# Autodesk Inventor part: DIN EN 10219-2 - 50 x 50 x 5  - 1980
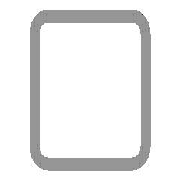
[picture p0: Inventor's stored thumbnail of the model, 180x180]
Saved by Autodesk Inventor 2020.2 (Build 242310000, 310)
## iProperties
IsCustomPart: 1
_CCFamilyMember: 16
_CCFamilyDisplayName: DIN EN 10219-2 (Quadratisches Hohlprofil - Kaltgeformt) - Kaltgeformte, geschweißte Baustahl-Hohlprofile aus unlegiertem Feinkorn-Baustahl
_FrameMemberDoc: Frame Member File
_Version: 15.0.0
_GetPNFromCC: 1
Created: 2019-01
Part Number: DIN EN 10219-2 - 50 x 50 x 5  - 1980
Material: Stahl, weich
Description: Kaltgeformte, geschweißte Baustahl-Hohlprofile aus unlegiertem Feinkorn-Baustahl
Document SubType Name: Modeling
Standard: DIN
Designer: lutzd
Standard Revision: 2006-07
Standards Organization: DIN
Language: de-DE
Size Designation: 50 x 50 x 5
Categories: <MemberInstance><Categories><Category DisplayName="Profile" InternalName="089c4875-fa83-4c05-b084-43b9cc11f5ed" Mnemonic="GRDR"><CategoryParameter DisplayName="
Stock Number: 50 x 50 x 5
Mass: 12983.3 g
Surface Area: 6638.25 cm^2
Volume: 1653.92 cm^3
Density: 7.85 g/cm^3
Appearance: Semi-Polished(8)
G_W: 50,000 mm
G_H: 50,000 mm
DocNumber: ADSK-014372
Folder: .
Mass: 12,983 kg
VLT_Material: Stahl, weich
+D1DB0533-E9D4-4803-9B6B-234758CD5357+SCHNITTDETAIL1: Schnittwinkel 90,00 grd
Dimensions: 50x50x1980 mm
G_L: 1980,000 mm
+D0B73FBA-8EAB-436B-AC1B-9B953FEEEDB6+SCHNITTDETAIL3: Schnittwinkel 90,00 grd
Title: Profil-Bauteil
Author: lutzd
Revision Number: -
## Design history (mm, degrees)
node "Startebene"
node "Endebene"
sketch "Skizze"
  geometry: L1 (-25, -15)-(-25, 15); L2 (-15, 25)-(15, 25); L3 (25, 15)-(25, -15); L4 (15, -25)-(-15, -25); L5 (-15, 20)-(15, 20); L6 (20, 15)-(20, -15); L7 (15, -20)-(-15, -20); L8 (-20, -15)-(-20, 15); L9 (0, 37.899)-(0, -37.899) reference; L10 (-37.899, 0)-(37.899, 0) reference; A1 r 10 centre (-15, -15) between (-25, -15) and (-15, -25); A2 r 10 centre (-15, 15) between (-15, 25) and (-25, 15); A3 r 10 centre (15, 15) between (25, 15) and (15, 25); A4 r 10 centre (15, -15) between (15, -25) and (25, -15); A5 r 5 centre (-15, 15) between (-15, 20) and (-20, 15); A6 r 5 centre (15, 15) between (20, 15) and (15, 20); A7 r 5 centre (15, -15) between (15, -20) and (20, -15); A8 r 5 centre (-15, -15) between (-20, -15) and (-15, -20)
  constraints: 16 end point, 16 point on circle, 8 centre point, 8 tangent, 4 parallel, 3 equal radius, 2 perpendicular, 7 other
  dimensions: "d7" = 10 radius of A1 (= G_IR); "d10" = 50 distance between parallel lines of L2 L4 (= G_H); "d11" = 50 distance between parallel lines of L1 L3 (= G_W); "d12" = 5 distance between parallel lines of L3 L6 (= G_T); "d15" = 25 distance between parallel lines of L2 L10 (= 0.5 x d10); "d16" = 25 distance between parallel lines of L9 L3 (= 0.5 x d11)
extrude "Körper" new body sketch "Skizze" stored distance "d3" = 1980 (= G_L); taper "d4" = 0 deg
node "Driven Length"
  sketch "Sketch3"
    geometry: L1 (0, 0)-(10, 0) reference
    constraints: 2 end point, 1 horizontal
  workplane "Work Plane3"
  sketch "Sketch4"
    geometry: L1 (-2, 50)-(12, 50) reference; L2 (-2, 2030)-(12, 2030) reference
    dimensions: "d18" = 1980 distance between parallel lines of L1 L2 (derived)
workplane "Arbeitsebene4"
feature "Trennen1"
sketch "Skizze5"
  geometry: L1 (0, -30)-(0, 0) reference; L2 (1980, -30)-(1980, 0) reference; 12 further points
  constraints: 2 midpoint, 12 other
  dimensions: "d19" = 200 distance of point (1190, -15) point (990, -15); "d20" = 200 distance of point (1190, -15) point (1390, -15) (= d19); "d21" = 200 distance of point (1390, -15) point (1590, -15) (= d19); "d22" = 200 distance of point (1790, -15) point (1590, -15) (= d19); "d23" = 200 distance of point (390, -15) point (190, -15) (= d19); "d24" = 200 distance of point (590, -15) point (390, -15) (= d19); "d25" = 200 distance of point (790, -15) point (590, -15) (= d19); "d26" = 200 distance of point (990, -15) point (790, -15) (= d19)
hole "Bohrung1" sketch "Skizze5" at (990, -15), (790, -15), (590, -15), (390, -15), (190, -15), (1190, -15), (1390, -15), (1590, -15), (1790, -15) diameter "d27" = 4.134; stored, may be unused: countersink angle "d31" = 90 deg, drill point angle "d33" = 118 deg; dims "d28" = 10, "d29" = 4, "d30" = 2, "d32" = 8
workplane "Arbeitsebene6"
feature "Trennen3"
body "Solid1"
other parameters: "G_W" = 50 [user parameter; used in 1 equation term], "G_H" = 50 [user parameter; used in 1 equation term], "G_T" = 5 [user parameter; used in 1 equation term], "G_IR" = 10 [user parameter; used in 1 equation term], "G_L" = 1980 (= d18) [user parameter; used in 1 equation term], "d17" = 90 deg
